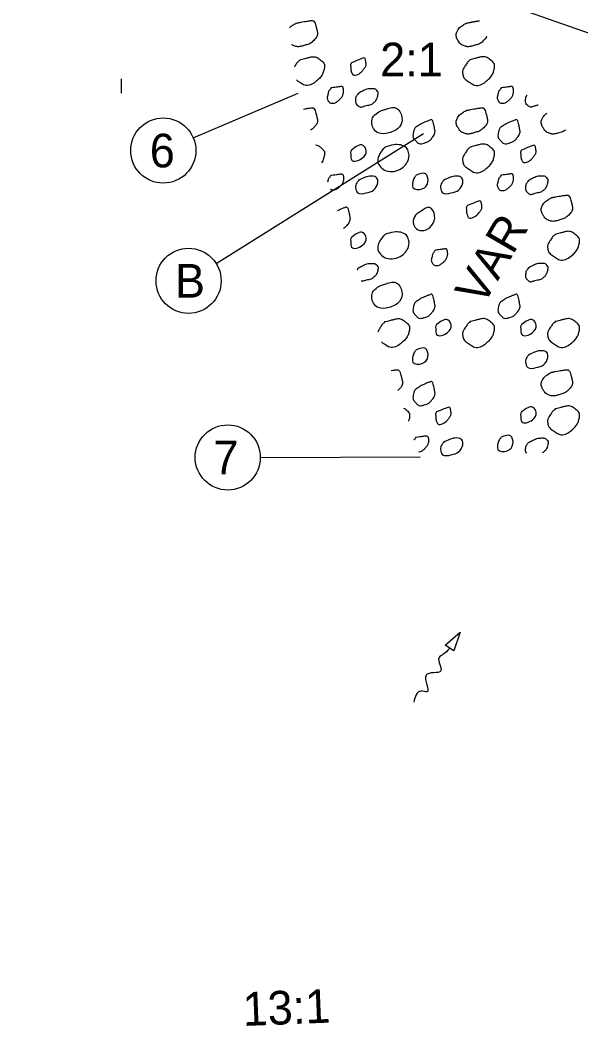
# Model space of a CAD drawing. Extents: x -1270 to 3371, y -118 to 220.
# Drawn here: x 75.77 to 99.09, y 112.18 to 154 of the extents above; entities that cross this region are included whole.
import ezdxf

# ---------------------------------------------------------------- set-up
doc = ezdxf.new("R2010")
doc.units = 0
for name, color, linetype in [('GE_P_Alignment', 7, 'Continuous'), ('GE_P_Alignment_100_Bearings', 7, 'Continuous'), ('GE_P_Alignment_100_Stations', 7, 'Continuous'), ('PV_P_EOP', 7, 'Continuous'), ('TX_P_1', 7, 'Continuous')]:
    doc.layers.add(name, color=color, linetype=linetype)

msp = doc.modelspace()

# ---------------------------------------------------------------- linework, layer by layer
at = {"layer": 'GE_P_Alignment'}
for p, q in [((82.968, 149.109), (87.329, 150.963)), ((83.921, 143.881), (92.541, 149.282)), ((85.756, 135.82), (92.4, 135.838))]:
    msp.add_line(p, q, dxfattribs=at)
at = {"layer": 'GE_P_Alignment_100_Bearings'}
for points, degree in [([(86.97, 153.676), (87.007, 153.716), (87.049, 153.752), (87.096, 153.782), (87.17, 153.829), (87.24, 153.873), (87.322, 153.891), (87.35, 153.897), (87.377, 153.902), (87.405, 153.908)], 3), ([(87.396, 153.907), (87.548, 153.932), (87.699, 153.961), (87.85, 153.982), (88.002, 154.003), (88.072, 153.744), (88.11, 153.602), (88.144, 153.473), (88.122, 153.316), (88.013, 153.196), (87.88, 153.048), (87.732, 152.992), (87.567, 152.943), (87.426, 152.902), (87.268, 152.886), (87.127, 152.946), (87.104, 152.955), (87.082, 152.967), (87.062, 152.981)], 3), ([(95.168, 153.334), (95.15, 153.285), (95.123, 153.238), (95.085, 153.196), (94.951, 153.048), (94.803, 152.992), (94.639, 152.943), (94.497, 152.902), (94.339, 152.886), (94.199, 152.946), (94.113, 152.982), (94.051, 153.044), (94, 153.124), (93.913, 153.258), (93.887, 153.443), (93.963, 153.569), (94.013, 153.653), (94.081, 153.727), (94.168, 153.782), (94.242, 153.829), (94.312, 153.873), (94.394, 153.891), (94.421, 153.897), (94.449, 153.902), (94.476, 153.908)], 3), ([(94.468, 153.907), (94.601, 153.929), (94.735, 153.955), (94.869, 153.975)], 2), ([(87.184, 152.062), (87.189, 152.07), (87.193, 152.077), (87.198, 152.085), (87.241, 152.153), (87.279, 152.222), (87.336, 152.277), (87.363, 152.303), (87.39, 152.329), (87.417, 152.355)], 3), ([(87.417, 152.355), (87.536, 152.386), (87.654, 152.417), (87.773, 152.448), (87.946, 152.493), (88.12, 152.461), (88.294, 152.317), (88.428, 152.204), (88.437, 152.038), (88.401, 151.914), (88.356, 151.757), (88.257, 151.609), (88.105, 151.479), (87.915, 151.317), (87.651, 151.253), (87.457, 151.368), (87.388, 151.409), (87.316, 151.46), (87.256, 151.517)], 3), ([(89.554, 152.229), (89.712, 152.293), (89.87, 152.361), (90.029, 152.422), (90.107, 152.451), (90.148, 152.278), (90.155, 152.203), (90.164, 152.104), (90.088, 151.999), (90.005, 151.901), (89.894, 151.767), (89.613, 151.669), (89.555, 151.817), (89.525, 151.895), (89.519, 151.976), (89.516, 152.057), (89.515, 152.097), (89.499, 152.141), (89.52, 152.177), (89.531, 152.196), (89.543, 152.212), (89.554, 152.229)], 3), ([(94.489, 152.355), (94.607, 152.386), (94.726, 152.417), (94.845, 152.448), (95.018, 152.493), (95.192, 152.461), (95.365, 152.317), (95.5, 152.204), (95.508, 152.038), (95.473, 151.914), (95.428, 151.757), (95.329, 151.609), (95.177, 151.479), (94.987, 151.317), (94.723, 151.253), (94.529, 151.368), (94.371, 151.461), (94.205, 151.601), (94.175, 151.767), (94.156, 151.869), (94.209, 151.989), (94.27, 152.085), (94.313, 152.153), (94.351, 152.222), (94.408, 152.277), (94.435, 152.303), (94.462, 152.329), (94.489, 152.355)], 3), ([(88.708, 151.182), (88.835, 151.2), (88.962, 151.221), (89.09, 151.238), (89.203, 151.253), (89.23, 151.008), (89.194, 150.909), (89.154, 150.801), (89.056, 150.693), (88.954, 150.615), (88.849, 150.535), (88.628, 150.548), (88.567, 150.672), (88.529, 150.75), (88.548, 150.84), (88.57, 150.918), (88.585, 150.973), (88.592, 151.036), (88.628, 151.081), (88.655, 151.115), (88.681, 151.148), (88.708, 151.182)], 3), ([(89.845, 150.965), (89.929, 151.007), (90.012, 151.049), (90.095, 151.09), (90.187, 151.136), (90.296, 151.145), (90.396, 151.148), (90.47, 151.15), (90.541, 151.133), (90.607, 151.067), (90.668, 151.007), (90.659, 150.927), (90.641, 150.864), (90.612, 150.759), (90.572, 150.652), (90.47, 150.567), (90.37, 150.484), (90.264, 150.472), (90.157, 150.447), (90.044, 150.421), (89.915, 150.354), (89.805, 150.453), (89.733, 150.518), (89.718, 150.594), (89.72, 150.669), (89.721, 150.735), (89.729, 150.813), (89.771, 150.869), (89.796, 150.901), (89.821, 150.933), (89.845, 150.965)], 3), ([(95.78, 151.182), (95.907, 151.2), (96.034, 151.221), (96.161, 151.238), (96.275, 151.253), (96.301, 151.008), (96.265, 150.909), (96.226, 150.801), (96.127, 150.693), (96.025, 150.615), (95.921, 150.535), (95.7, 150.548), (95.639, 150.672), (95.6, 150.75), (95.62, 150.84), (95.641, 150.918), (95.656, 150.973), (95.664, 151.036), (95.7, 151.081), (95.726, 151.115), (95.753, 151.148), (95.78, 151.182)], 3), ([(97.314, 150.466), (97.286, 150.459), (97.257, 150.454), (97.229, 150.447), (97.116, 150.421), (96.987, 150.354), (96.877, 150.453), (96.804, 150.518), (96.789, 150.594), (96.791, 150.669), (96.793, 150.735), (96.801, 150.813), (96.843, 150.869), (96.847, 150.874), (96.851, 150.879), (96.855, 150.884)], 3), ([(87.551, 150.303), (87.65, 150.321), (87.75, 150.338), (87.85, 150.352), (88.002, 150.373), (88.072, 150.114), (88.11, 149.972), (88.144, 149.843), (88.122, 149.686), (88.013, 149.565), (87.959, 149.506), (87.903, 149.461), (87.845, 149.426)], 3), ([(94.468, 150.276), (94.619, 150.302), (94.771, 150.331), (94.922, 150.352), (95.073, 150.373), (95.143, 150.114), (95.181, 149.972), (95.216, 149.843), (95.193, 149.686), (95.085, 149.565), (94.951, 149.418), (94.803, 149.361), (94.639, 149.313), (94.497, 149.271), (94.339, 149.256), (94.199, 149.315), (94.113, 149.351), (94.051, 149.413), (94, 149.494), (93.913, 149.627), (93.887, 149.812), (93.963, 149.939), (94.013, 150.022), (94.081, 150.096), (94.168, 150.152), (94.242, 150.199), (94.312, 150.243), (94.394, 150.26), (94.421, 150.266), (94.449, 150.272), (94.476, 150.278)], 3), ([(92.448, 149.694), (92.565, 149.744), (92.682, 149.794), (92.8, 149.844), (92.921, 149.897), (92.98, 149.63), (93.007, 149.506), (93.035, 149.375), (93.001, 149.228), (92.895, 149.101), (92.796, 148.982), (92.682, 148.925), (92.562, 148.889), (92.466, 148.86), (92.345, 148.855), (92.251, 148.948), (92.137, 149.06), (92.095, 149.192), (92.118, 149.307), (92.136, 149.398), (92.179, 149.518), (92.264, 149.574), (92.325, 149.615), (92.387, 149.654), (92.448, 149.694)], 3), ([(95.984, 149.694), (96.101, 149.744), (96.218, 149.794), (96.335, 149.844), (96.457, 149.897), (96.516, 149.63), (96.543, 149.506), (96.571, 149.375), (96.537, 149.228), (96.431, 149.101), (96.331, 148.982), (96.218, 148.925), (96.098, 148.889), (96.002, 148.86), (95.881, 148.855), (95.787, 148.948), (95.673, 149.06), (95.631, 149.192), (95.654, 149.307), (95.672, 149.398), (95.714, 149.518), (95.8, 149.574), (95.861, 149.615), (95.922, 149.654), (95.984, 149.694)], 3), ([(98.455, 149.428), (98.368, 149.374), (98.274, 149.342), (98.175, 149.313), (98.033, 149.271), (97.875, 149.256), (97.735, 149.315), (97.649, 149.351), (97.587, 149.413), (97.535, 149.494), (97.449, 149.627), (97.423, 149.812), (97.499, 149.939), (97.544, 150.014), (97.603, 150.082), (97.678, 150.135)], 3), ([(88.048, 148.819), (88.13, 148.798), (88.212, 148.754), (88.294, 148.686), (88.428, 148.574), (88.437, 148.408), (88.401, 148.284), (88.38, 148.209), (88.346, 148.136), (88.3, 148.066)], 3), ([(94.489, 148.724), (94.607, 148.756), (94.726, 148.787), (94.845, 148.818), (95.018, 148.863), (95.192, 148.831), (95.365, 148.686), (95.5, 148.574), (95.508, 148.408), (95.473, 148.284), (95.428, 148.127), (95.329, 147.978), (95.177, 147.849), (94.987, 147.686), (94.723, 147.623), (94.529, 147.738), (94.371, 147.831), (94.205, 147.971), (94.175, 148.136), (94.156, 148.239), (94.209, 148.359), (94.27, 148.454), (94.313, 148.523), (94.351, 148.592), (94.408, 148.647), (94.435, 148.673), (94.462, 148.699), (94.489, 148.724)], 3), ([(96.625, 148.599), (96.784, 148.663), (96.942, 148.731), (97.1, 148.791), (97.178, 148.821), (97.219, 148.647), (97.226, 148.573), (97.236, 148.473), (97.159, 148.369), (97.077, 148.27), (96.965, 148.136), (96.685, 148.039), (96.627, 148.186), (96.596, 148.264), (96.591, 148.345), (96.588, 148.426), (96.586, 148.466), (96.571, 148.511), (96.592, 148.547), (96.603, 148.565), (96.614, 148.581), (96.625, 148.599)], 3), ([(88.566, 147.274), (88.567, 147.279), (88.568, 147.283), (88.57, 147.287), (88.585, 147.342), (88.592, 147.405), (88.628, 147.451), (88.655, 147.484), (88.681, 147.518), (88.708, 147.551)], 3), ([(88.708, 147.551), (88.835, 147.57), (88.962, 147.59), (89.09, 147.607), (89.203, 147.623), (89.23, 147.377), (89.194, 147.279), (89.154, 147.171), (89.056, 147.063), (88.954, 146.985), (88.885, 146.932), (88.765, 146.92), (88.674, 146.953)], 3), ([(95.78, 147.551), (95.907, 147.57), (96.034, 147.59), (96.161, 147.607), (96.275, 147.623), (96.301, 147.377), (96.265, 147.279), (96.226, 147.171), (96.127, 147.063), (96.025, 146.985), (95.921, 146.904), (95.7, 146.918), (95.639, 147.041), (95.6, 147.119), (95.62, 147.209), (95.641, 147.287), (95.656, 147.342), (95.664, 147.405), (95.7, 147.451), (95.726, 147.484), (95.753, 147.518), (95.78, 147.551)], 3), ([(96.917, 147.335), (97, 147.377), (97.083, 147.418), (97.167, 147.46), (97.259, 147.505), (97.368, 147.514), (97.468, 147.517), (97.541, 147.519), (97.612, 147.502), (97.679, 147.436), (97.739, 147.376), (97.731, 147.296), (97.713, 147.233), (97.683, 147.128), (97.644, 147.021), (97.542, 146.936), (97.442, 146.853), (97.336, 146.841), (97.229, 146.816), (97.116, 146.79), (96.987, 146.723), (96.877, 146.822), (96.804, 146.888), (96.789, 146.964), (96.791, 147.038), (96.793, 147.104), (96.801, 147.183), (96.843, 147.238), (96.867, 147.271), (96.892, 147.303), (96.917, 147.335)], 3), ([(94.37, 146.288), (94.528, 146.352), (94.686, 146.42), (94.845, 146.48), (94.922, 146.51), (94.963, 146.336), (94.97, 146.262), (94.98, 146.162), (94.903, 146.058), (94.821, 145.959), (94.71, 145.825), (94.429, 145.728), (94.371, 145.875), (94.341, 145.954), (94.335, 146.034), (94.332, 146.115), (94.331, 146.156), (94.315, 146.2), (94.336, 146.236), (94.347, 146.254), (94.359, 146.27), (94.37, 146.288)], 3), ([(98.004, 146.646), (98.155, 146.671), (98.307, 146.7), (98.458, 146.721), (98.609, 146.742), (98.679, 146.483), (98.717, 146.341), (98.751, 146.213), (98.729, 146.055), (98.62, 145.935), (98.487, 145.787), (98.339, 145.731), (98.175, 145.682), (98.033, 145.641), (97.875, 145.625), (97.735, 145.685), (97.649, 145.721), (97.587, 145.783), (97.535, 145.863), (97.449, 145.997), (97.423, 146.182), (97.499, 146.308), (97.549, 146.392), (97.617, 146.466), (97.704, 146.521), (97.777, 146.568), (97.848, 146.612), (97.93, 146.63), (97.957, 146.636), (97.985, 146.641), (98.012, 146.647)], 3), ([(88.965, 146.086), (89.064, 146.128), (89.164, 146.171), (89.264, 146.214), (89.385, 146.266), (89.445, 145.999), (89.471, 145.876), (89.499, 145.745), (89.466, 145.598), (89.36, 145.471), (89.314, 145.416), (89.265, 145.374), (89.214, 145.341)], 3), ([(98.025, 145.094), (98.143, 145.126), (98.262, 145.156), (98.38, 145.187), (98.554, 145.232), (98.728, 145.2), (98.901, 145.056), (99.036, 144.943), (99.044, 144.777), (99.009, 144.653), (98.964, 144.496), (98.865, 144.348), (98.713, 144.218), (98.523, 144.056), (98.259, 143.992), (98.065, 144.107), (97.907, 144.201), (97.741, 144.34), (97.71, 144.506), (97.691, 144.608), (97.745, 144.728), (97.805, 144.824), (97.848, 144.892), (97.887, 144.961), (97.944, 145.016), (97.971, 145.042), (97.997, 145.068), (98.025, 145.094)], 3), ([(93.038, 144.432), (93.165, 144.45), (93.292, 144.47), (93.42, 144.487), (93.533, 144.503), (93.56, 144.257), (93.524, 144.159), (93.484, 144.051), (93.386, 143.943), (93.284, 143.865), (93.179, 143.785), (92.958, 143.798), (92.897, 143.922), (92.859, 143.999), (92.878, 144.089), (92.9, 144.167), (92.915, 144.222), (92.922, 144.285), (92.958, 144.331), (92.985, 144.364), (93.011, 144.398), (93.038, 144.432)], 3), ([(89.845, 143.704), (89.929, 143.746), (90.012, 143.788), (90.095, 143.829), (90.187, 143.875), (90.296, 143.884), (90.396, 143.887), (90.47, 143.889), (90.541, 143.872), (90.607, 143.806), (90.668, 143.746), (90.659, 143.666), (90.641, 143.603), (90.612, 143.498), (90.572, 143.391), (90.47, 143.306), (90.37, 143.223), (90.264, 143.211), (90.157, 143.186), (90.092, 143.171), (90.021, 143.142), (89.952, 143.14)], 3), ([(96.917, 143.704), (97, 143.746), (97.083, 143.788), (97.167, 143.829), (97.259, 143.875), (97.368, 143.884), (97.468, 143.887), (97.541, 143.889), (97.612, 143.872), (97.679, 143.806), (97.739, 143.746), (97.731, 143.666), (97.713, 143.603), (97.683, 143.498), (97.644, 143.391), (97.542, 143.306), (97.442, 143.223), (97.336, 143.211), (97.229, 143.186), (97.116, 143.16), (96.987, 143.093), (96.877, 143.192), (96.804, 143.257), (96.789, 143.333), (96.791, 143.408), (96.793, 143.474), (96.801, 143.552), (96.843, 143.608), (96.867, 143.64), (96.892, 143.672), (96.917, 143.704)], 3), ([(89.788, 143.63), (89.807, 143.655), (89.826, 143.679), (89.845, 143.704)], 2), ([(92.448, 142.433), (92.565, 142.483), (92.682, 142.533), (92.8, 142.583), (92.921, 142.636), (92.98, 142.369), (93.007, 142.245), (93.035, 142.114), (93.001, 141.967), (92.895, 141.84), (92.796, 141.721), (92.682, 141.664), (92.562, 141.628), (92.466, 141.599), (92.345, 141.594), (92.251, 141.687), (92.137, 141.799), (92.095, 141.931), (92.118, 142.046), (92.136, 142.137), (92.179, 142.257), (92.264, 142.313), (92.325, 142.354), (92.387, 142.393), (92.448, 142.433)], 3), ([(95.984, 142.433), (96.101, 142.483), (96.218, 142.533), (96.335, 142.583), (96.457, 142.636), (96.516, 142.369), (96.543, 142.245), (96.571, 142.114), (96.537, 141.967), (96.431, 141.84), (96.331, 141.721), (96.218, 141.664), (96.098, 141.628), (96.002, 141.599), (95.881, 141.594), (95.787, 141.687), (95.673, 141.799), (95.631, 141.931), (95.654, 142.046), (95.672, 142.137), (95.714, 142.257), (95.8, 142.313), (95.861, 142.354), (95.922, 142.393), (95.984, 142.433)], 3), ([(90.657, 141.038), (90.675, 141.092), (90.704, 141.146), (90.734, 141.193), (90.777, 141.262), (90.815, 141.331), (90.872, 141.386), (90.899, 141.412), (90.926, 141.438), (90.953, 141.463)], 3), ([(90.953, 141.463), (91.071, 141.495), (91.19, 141.526), (91.309, 141.557), (91.482, 141.602), (91.656, 141.57), (91.83, 141.425), (91.964, 141.313), (91.973, 141.147), (91.937, 141.023), (91.892, 140.866), (91.793, 140.717), (91.641, 140.588), (91.451, 140.425), (91.187, 140.362), (90.993, 140.477), (90.925, 140.517), (90.856, 140.565), (90.797, 140.621)], 3), ([(94.489, 141.463), (94.607, 141.495), (94.726, 141.526), (94.845, 141.557), (95.018, 141.602), (95.192, 141.57), (95.365, 141.425), (95.5, 141.313), (95.508, 141.147), (95.473, 141.023), (95.428, 140.866), (95.329, 140.717), (95.177, 140.588), (94.987, 140.425), (94.723, 140.362), (94.529, 140.477), (94.371, 140.57), (94.205, 140.71), (94.175, 140.875), (94.156, 140.978), (94.209, 141.098), (94.27, 141.193), (94.313, 141.262), (94.351, 141.331), (94.408, 141.386), (94.435, 141.412), (94.462, 141.438), (94.489, 141.463)], 3), ([(98.025, 141.463), (98.143, 141.495), (98.262, 141.526), (98.38, 141.557), (98.554, 141.602), (98.728, 141.57), (98.901, 141.425), (99.036, 141.313), (99.044, 141.147), (99.009, 141.023), (98.964, 140.866), (98.865, 140.717), (98.713, 140.588), (98.523, 140.425), (98.259, 140.362), (98.065, 140.477), (97.907, 140.57), (97.741, 140.71), (97.71, 140.875), (97.691, 140.978), (97.745, 141.098), (97.805, 141.193), (97.848, 141.262), (97.887, 141.331), (97.944, 141.386), (97.971, 141.412), (97.997, 141.438), (98.025, 141.463)], 3), ([(91.196, 139.431), (91.259, 139.441), (91.323, 139.452), (91.386, 139.46), (91.537, 139.482), (91.608, 139.222), (91.645, 139.08), (91.68, 138.952), (91.657, 138.794), (91.549, 138.674), (91.524, 138.647), (91.499, 138.623), (91.474, 138.601)], 3), ([(98.004, 139.385), (98.155, 139.411), (98.307, 139.439), (98.458, 139.46), (98.609, 139.482), (98.679, 139.222), (98.717, 139.08), (98.751, 138.952), (98.729, 138.794), (98.62, 138.674), (98.487, 138.526), (98.339, 138.47), (98.175, 138.421), (98.033, 138.38), (97.875, 138.365), (97.735, 138.424), (97.649, 138.46), (97.587, 138.522), (97.535, 138.602), (97.449, 138.736), (97.423, 138.921), (97.499, 139.047), (97.549, 139.131), (97.617, 139.205), (97.704, 139.26), (97.777, 139.307), (97.848, 139.351), (97.93, 139.369), (97.957, 139.375), (97.985, 139.38), (98.012, 139.386)], 3), ([(92.448, 138.802), (92.565, 138.852), (92.682, 138.903), (92.8, 138.953), (92.921, 139.005), (92.98, 138.738), (93.007, 138.615), (93.035, 138.484), (93.001, 138.337), (92.895, 138.21), (92.796, 138.09), (92.682, 138.033), (92.562, 137.997), (92.466, 137.968), (92.345, 137.963), (92.251, 138.056), (92.137, 138.169), (92.095, 138.301), (92.118, 138.415), (92.136, 138.506), (92.179, 138.626), (92.264, 138.683), (92.325, 138.724), (92.387, 138.762), (92.448, 138.802)], 3), ([(91.718, 137.872), (91.755, 137.851), (91.792, 137.826), (91.83, 137.795), (91.964, 137.682), (91.973, 137.516), (91.937, 137.392), (91.929, 137.364), (91.919, 137.336), (91.907, 137.308)], 3), ([(93.09, 137.707), (93.248, 137.771), (93.406, 137.839), (93.565, 137.9), (93.642, 137.929), (93.683, 137.756), (93.69, 137.681), (93.7, 137.582), (93.623, 137.478), (93.541, 137.379), (93.43, 137.245), (93.149, 137.147), (93.091, 137.295), (93.06, 137.373), (93.055, 137.454), (93.052, 137.535), (93.05, 137.575), (93.035, 137.619), (93.056, 137.655), (93.067, 137.674), (93.079, 137.69), (93.09, 137.707)], 3), ([(98.025, 137.833), (98.143, 137.865), (98.262, 137.896), (98.38, 137.926), (98.554, 137.971), (98.728, 137.939), (98.901, 137.795), (99.036, 137.682), (99.044, 137.516), (99.009, 137.392), (98.964, 137.235), (98.865, 137.087), (98.713, 136.957), (98.523, 136.795), (98.259, 136.731), (98.065, 136.846), (97.907, 136.94), (97.741, 137.08), (97.71, 137.245), (97.691, 137.347), (97.745, 137.467), (97.805, 137.563), (97.848, 137.631), (97.887, 137.7), (97.944, 137.755), (97.971, 137.781), (97.997, 137.807), (98.025, 137.833)], 3), ([(92.16, 136.554), (92.161, 136.556), (92.162, 136.558), (92.164, 136.559), (92.19, 136.593), (92.217, 136.626), (92.244, 136.66)], 3), ([(92.244, 136.66), (92.371, 136.678), (92.498, 136.699), (92.625, 136.716), (92.739, 136.731), (92.765, 136.486), (92.73, 136.387), (92.69, 136.279), (92.591, 136.171), (92.49, 136.093), (92.449, 136.062), (92.391, 136.045), (92.331, 136.043)], 3), ([(96.832, 135.982), (96.798, 136.035), (96.79, 136.091), (96.791, 136.147), (96.793, 136.213), (96.801, 136.291), (96.843, 136.347), (96.867, 136.379), (96.892, 136.411), (96.917, 136.443)], 3), ([(96.917, 136.443), (97, 136.485), (97.083, 136.527), (97.167, 136.568), (97.259, 136.614), (97.368, 136.623), (97.468, 136.626), (97.541, 136.628), (97.612, 136.611), (97.679, 136.545), (97.739, 136.485), (97.731, 136.405), (97.713, 136.342), (97.683, 136.237), (97.644, 136.13), (97.542, 136.045), (97.522, 136.029), (97.503, 136.015), (97.483, 136.004)], 3)]:
    msp.add_open_spline(points, degree=degree, dxfattribs=at)
for points in [[(90.932, 150.276), (91.386, 150.352), (91.645, 149.972), (91.549, 149.565), (91.103, 149.313), (90.663, 149.315), (90.464, 149.494), (90.427, 149.939), (90.632, 150.152), (90.858, 150.26), (90.94, 150.278)], [(89.554, 148.599), (90.029, 148.791), (90.155, 148.573), (90.005, 148.27), (89.555, 148.186), (89.516, 148.426), (89.52, 148.547), (89.554, 148.599)], [(90.953, 148.724), (91.309, 148.818), (91.83, 148.686), (91.937, 148.284), (91.641, 147.849), (90.993, 147.738), (90.639, 148.136), (90.734, 148.454), (90.872, 148.647), (90.953, 148.724)], [(92.244, 147.551), (92.625, 147.607), (92.73, 147.279), (92.49, 146.985), (92.103, 147.041), (92.105, 147.287), (92.164, 147.451), (92.244, 147.551)], [(89.845, 147.335), (90.095, 147.46), (90.396, 147.517), (90.607, 147.436), (90.641, 147.233), (90.47, 146.936), (90.157, 146.816), (89.805, 146.822), (89.72, 147.038), (89.771, 147.238), (89.845, 147.335)], [(93.381, 147.335), (93.631, 147.46), (93.932, 147.517), (94.143, 147.436), (94.177, 147.233), (94.006, 146.936), (93.693, 146.816), (93.341, 146.822), (93.255, 147.038), (93.307, 147.238), (93.381, 147.335)], [(92.448, 146.063), (92.8, 146.214), (93.007, 145.876), (92.895, 145.471), (92.562, 145.258), (92.251, 145.317), (92.118, 145.676), (92.264, 145.944), (92.448, 146.063)], [(89.554, 144.968), (90.029, 145.161), (90.155, 144.942), (90.005, 144.64), (89.555, 144.556), (89.516, 144.796), (89.52, 144.916), (89.554, 144.968)], [(90.953, 145.094), (91.309, 145.187), (91.83, 145.056), (91.937, 144.653), (91.641, 144.218), (90.993, 144.107), (90.639, 144.506), (90.734, 144.824), (90.872, 145.016), (90.953, 145.094)], [(90.932, 143.015), (91.386, 143.091), (91.645, 142.711), (91.549, 142.304), (91.103, 142.052), (90.663, 142.054), (90.464, 142.233), (90.427, 142.678), (90.632, 142.891), (90.858, 142.999), (90.94, 143.017)], [(93.09, 141.338), (93.565, 141.53), (93.69, 141.312), (93.541, 141.009), (93.091, 140.925), (93.052, 141.165), (93.056, 141.286), (93.09, 141.338)], [(96.625, 141.338), (97.1, 141.53), (97.226, 141.312), (97.077, 141.009), (96.627, 140.925), (96.588, 141.165), (96.592, 141.286), (96.625, 141.338)], [(92.244, 140.29), (92.625, 140.346), (92.73, 140.018), (92.49, 139.724), (92.103, 139.78), (92.105, 140.026), (92.164, 140.19), (92.244, 140.29)], [(96.917, 140.074), (97.167, 140.199), (97.468, 140.256), (97.679, 140.175), (97.713, 139.972), (97.542, 139.675), (97.229, 139.555), (96.877, 139.561), (96.791, 139.777), (96.843, 139.977), (96.917, 140.074)], [(96.625, 137.707), (97.1, 137.9), (97.226, 137.681), (97.077, 137.379), (96.627, 137.295), (96.588, 137.535), (96.592, 137.655), (96.625, 137.707)], [(95.78, 136.66), (96.161, 136.716), (96.265, 136.387), (96.025, 136.093), (95.639, 136.15), (95.641, 136.396), (95.7, 136.559), (95.78, 136.66)], [(93.381, 136.443), (93.631, 136.568), (93.932, 136.626), (94.143, 136.545), (94.177, 136.342), (94.006, 136.045), (93.693, 135.925), (93.341, 135.931), (93.255, 136.147), (93.307, 136.347), (93.381, 136.443)]]:
    msp.add_spline(points, degree=3, dxfattribs=at)
at = {"layer": 'GE_P_Alignment_100_Stations'}
for p, q in [((93.449, 128.007), (94.07, 128.556)), ((94.07, 128.556), (93.807, 127.77)), ((93.807, 127.77), (93.449, 128.007))]:
    msp.add_line(p, q, dxfattribs=at)
msp.add_spline([(93.627, 127.89), (93.61, 127.864), (93.365, 127.631), (93.19, 127.497), (93.262, 126.941), (92.651, 126.764), (92.686, 126.069), (92.437, 126.098), (92.139, 125.636)], degree=3, dxfattribs=at)
at = {"layer": 'PV_P_EOP'}
msp.add_line((79.983, 150.963), (79.983, 151.563), dxfattribs=at)
at = {"layer": 'TX_P_1'}
msp.add_line((106.483, 150.963), (75.765, 161.784), dxfattribs=at)
for centre in [(81.721, 148.578), (82.773, 143.162), (84.401, 135.817)]:
    msp.add_circle(centre, 1.355, dxfattribs=at)

# ---------------------------------------------------------------- texts
for s, p in [('2:1', (90.74, 151.663)), ('6', (81.159, 147.878)), ('B', (82.207, 142.462)), ('7', (83.81, 135.117))]:
    msp.add_text(s, height=1.4, dxfattribs=at).set_placement(p)
for s, rotation, p in [('VAR', 59.7484, (95.002, 142.054)), ('13:1', 2.2498, (85.048, 112.175))]:
    msp.add_text(s, height=1.4, rotation=rotation, dxfattribs=at).set_placement(p)

doc.saveas('drawing.dxf')
